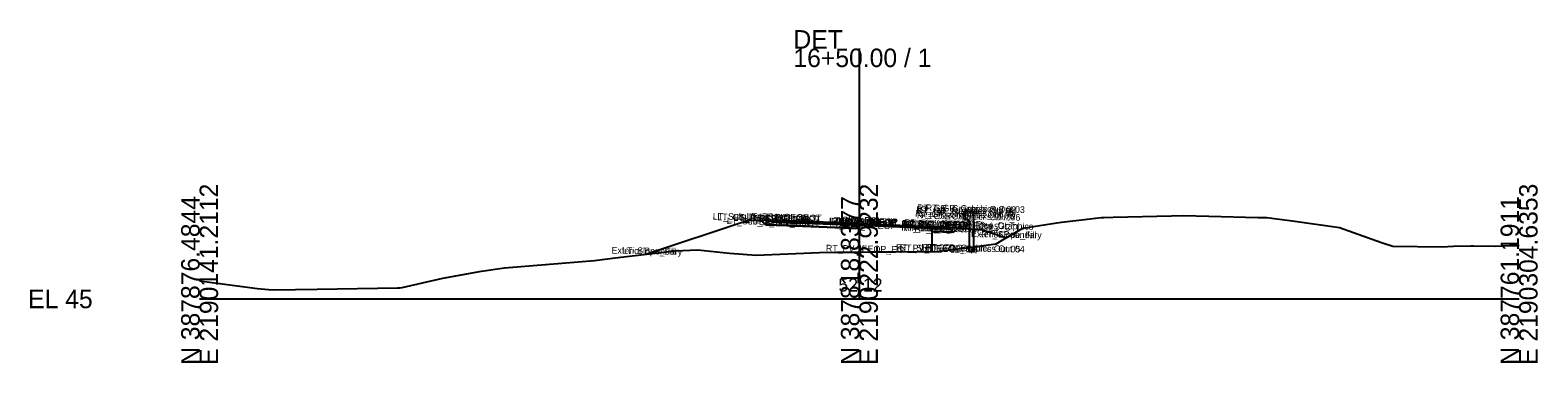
# Model space of a CAD drawing. Extents: x -26 to 1203, y -10 to 9543.
# Drawn here: x -25.7 to 202.8, y 6490.3 to 6540.8 of the extents above; entities that cross this region are included whole.
import ezdxf

# ---------------------------------------------------------------- set-up
doc = ezdxf.new("R2010")
doc.units = 0
for name, color, linetype in [('Default', 7, 'Continuous'), ('Exist CMT Pavement', 7, 'Continuous'), ('Exist Cross Section Cell', 7, 'Continuous'), ('Exist XS Center Line Elevation Label', 7, 'Continuous'), ('Exist XS Ground Line', 7, 'Continuous'), ('Prop CMT Guardrail Graphics', 7, 'Continuous'), ('Prop CMT Pvmt Course 1', 7, 'Continuous'), ('Prop CMT Pvmt Course 1 Wedge', 7, 'Continuous'), ('Prop CMT Pvmt Course 2', 7, 'Continuous'), ('Prop CMT Pvmt Course 2 Wedge', 7, 'Continuous'), ('Prop CMT Pvmt Course 3', 7, 'Continuous'), ('Prop CMT Pvmt Course 3 Wedge', 7, 'Continuous'), ('Prop CMT Pvmt Surface', 7, 'Continuous'), ('Prop CMT Pvmt Surface Shoulder', 7, 'Continuous'), ('Prop CMT Pvmt Wedge Surface 1', 7, 'Continuous'), ('Prop CMT Pvmt Wedge Surface 2', 7, 'Continuous'), ('Prop CMT Pvmt Wedge Surface 3', 7, 'Continuous'), ('Prop CMT Shld Paved Course 1', 7, 'Continuous'), ('Prop CMT Shld Paved Course 2', 7, 'Continuous'), ('Prop CMT Shld Paved Course 3', 7, 'Continuous'), ('Prop CMT Slope Grass', 7, 'Continuous'), ('Prop CMT Subgrade Earthwork', 7, 'Continuous'), ('Scratch_Level_0', 7, 'Continuous')]:
    doc.layers.add(name, color=color, linetype=linetype)

msp = doc.modelspace()

# ---------------------------------------------------------------- linework, layer by layer
at = {"layer": 'Exist CMT Pavement'}
msp.add_lwpolyline([(100, 6507.12), (111, 6507.18)], dxfattribs=at)
at = {"layer": 'Exist Cross Section Cell'}
for p, q in [((100, 6500), (100, 6537.97)), ((0, 6500), (100, 6500)), ((100, 6500), (200, 6500))]:
    msp.add_line(p, q, dxfattribs=at)
at = {"layer": 'Exist XS Ground Line'}
for p, q in [((124.76, 6510.72), (129.95, 6511.53)), ((129.95, 6511.53), (130.66, 6511.64)), ((130.66, 6511.64), (134.99, 6512.16)), ((134.99, 6512.16), (135.77, 6512.25)), ((135.77, 6512.25), (136.67, 6512.37)), ((136.67, 6512.37), (137.04, 6512.38)), ((137.04, 6512.38), (138.45, 6512.41)), ((138.45, 6512.41), (147.29, 6512.62)), ((147.29, 6512.62), (149.1, 6512.66)), ((149.1, 6512.66), (152.99, 6512.55)), ((152.99, 6512.55), (160.42, 6512.35)), ((160.42, 6512.35), (161.33, 6512.34)), ((161.33, 6512.34), (161.74, 6512.34)), ((161.74, 6512.34), (163.27, 6512.15)), ((163.27, 6512.15), (165.64, 6511.83)), ((165.64, 6511.83), (172.75, 6510.85)), ((120.74, 6508.37), (121.9, 6509.08)), ((121.9, 6509.08), (124.76, 6510.72)), ((172.75, 6510.85), (179.16, 6508.57)), ((62.97, 6506.24), (72.1, 6507.28)), ((72.1, 6507.28), (75.5, 6507.44)), ((75.5, 6507.44), (80.32, 6506.95)), ((80.32, 6506.95), (84.34, 6506.63)), ((84.34, 6506.63), (93.97, 6507.05)), ((93.97, 6507.05), (96.58, 6507.11)), ((96.58, 6507.11), (97.03, 6507.11)), ((97.03, 6507.11), (100, 6507.12)), ((100, 6507.12), (101.37, 6507.13)), ((101.37, 6507.13), (111.84, 6507.19)), ((111.84, 6507.19), (116.91, 6507.85)), ((116.91, 6507.85), (120.74, 6508.37)), ((179.16, 6508.57), (180.84, 6508.02)), ((180.84, 6508.02), (188.27, 6507.91)), ((188.27, 6507.91), (190.03, 6507.99)), ((190.03, 6507.99), (192.69, 6508.04)), ((192.69, 6508.04), (193.11, 6508.04)), ((193.11, 6508.04), (196.44, 6508.02)), ((196.44, 6508.02), (198.55, 6508.11)), ((198.55, 6508.11), (200, 6508.12)), ((36.88, 6503.17), (42.73, 6504.19)), ((42.73, 6504.19), (46.19, 6504.74)), ((46.19, 6504.74), (52.42, 6505.21)), ((52.42, 6505.21), (59.86, 6505.81)), ((59.86, 6505.81), (62.97, 6506.24)), ((0, 6502.73), (8.76, 6501.61)), ((30.36, 6501.68), (30.71, 6501.75)), ((30.71, 6501.75), (36.88, 6503.17)), ((8.76, 6501.61), (10.46, 6501.44)), ((10.46, 6501.44), (11.24, 6501.39)), ((11.24, 6501.39), (17.82, 6501.47)), ((17.82, 6501.47), (29.97, 6501.68)), ((29.97, 6501.68), (30.36, 6501.68))]:
    msp.add_line(p, q, dxfattribs=at)
at = {"layer": 'Prop CMT Guardrail Graphics'}
for points in [[(117.33, 6513.2), (116, 6513.2), (115.72, 6512.91)], [(117.33, 6507.2), (117.33, 6513.2)], [(115.72, 6512.91), (116, 6512.62)], [(116, 6512.62), (115.72, 6512.32)], [(115.72, 6512.32), (116, 6512.03), (116.66, 6512.03)], [(116.66, 6512.03), (116.66, 6507.2)], [(116.66, 6507.2), (117.33, 6507.2)]]:
    msp.add_lwpolyline(points, dxfattribs=at)
at = {"layer": 'Prop CMT Pvmt Course 1'}
for points in [[(100, 6511.43), (89, 6511.87)], [(89, 6511.87), (89, 6511.62)], [(89, 6511.62), (100, 6511.18)], [(100, 6511.18), (100, 6511.43)], [(100, 6511.43), (111, 6511)], [(100, 6511.18), (100, 6511.43)], [(111, 6510.87), (100, 6511.31)], [(100, 6511.31), (100, 6511.18), (100, 6511.18)], [(111, 6511), (111, 6510.75), (111, 6510.75), (111, 6510.87)]]:
    msp.add_lwpolyline(points, dxfattribs=at)
msp.add_lwpolyline([(100, 6511.18), (100, 6511.31), (100, 6511.31), (100, 6511.18)], close=True, dxfattribs=at)
at = {"layer": 'Prop CMT Pvmt Course 1 Wedge'}
msp.add_lwpolyline([(100, 6511.31), (111, 6510.87)], dxfattribs=at)
at = {"layer": 'Prop CMT Pvmt Course 2'}
for points in [[(89, 6511.62), (100, 6511.18)], [(100, 6511.18), (89, 6511.62)], [(89, 6511.62), (89, 6511.62)], [(100, 6511.18), (100, 6511.18)], [(111, 6510.75), (111, 6510.75)]]:
    msp.add_lwpolyline(points, dxfattribs=at)
msp.add_lwpolyline([(111, 6510.75), (111, 6510.75), (111, 6510.75)], close=True, dxfattribs=at)
at = {"layer": 'Prop CMT Pvmt Course 2 Wedge'}
msp.add_lwpolyline([(100, 6511.18), (111, 6510.75)], dxfattribs=at)
at = {"layer": 'Prop CMT Pvmt Course 3'}
for points in [[(100, 6511.18), (89, 6511.62)], [(89, 6511.62), (89, 6511.12)], [(89, 6511.12), (100, 6510.68)], [(100, 6510.68), (100, 6511.18)], [(111, 6510.75), (111, 6510.75), (111, 6510.25), (111, 6510.25)], [(111, 6510.25), (111, 6510.75)]]:
    msp.add_lwpolyline(points, dxfattribs=at)
at = {"layer": 'Prop CMT Pvmt Course 3 Wedge'}
msp.add_lwpolyline([(100, 6511.18), (111, 6510.75)], dxfattribs=at)
at = {"layer": 'Prop CMT Pvmt Surface'}
for points in [[(100, 6511.43), (89, 6511.87)], [(100, 6511.43), (111, 6511)]]:
    msp.add_lwpolyline(points, dxfattribs=at)
at = {"layer": 'Prop CMT Pvmt Surface Shoulder'}
for points in [[(89, 6511.87), (87, 6511.95)], [(111, 6511), (113, 6510.92)]]:
    msp.add_lwpolyline(points, dxfattribs=at)
at = {"layer": 'Prop CMT Pvmt Wedge Surface 1'}
for points in [[(100, 6511.31), (111, 6510.87)], [(111, 6510.75), (111, 6511)], [(111, 6510.87), (111, 6510.75), (111, 6510.75)]]:
    msp.add_lwpolyline(points, dxfattribs=at)
at = {"layer": 'Prop CMT Pvmt Wedge Surface 2'}
for points in [[(100, 6511.18), (111, 6510.75)], [(111, 6510.75), (111, 6511)]]:
    msp.add_lwpolyline(points, dxfattribs=at)
at = {"layer": 'Prop CMT Pvmt Wedge Surface 3'}
for points in [[(100, 6511.18), (111, 6510.75)], [(111, 6510.75), (111, 6511)]]:
    msp.add_lwpolyline(points, dxfattribs=at)
at = {"layer": 'Prop CMT Shld Paved Course 1'}
for points in [[(89, 6511.87), (87, 6511.95), (86.76, 6511.71)], [(86.76, 6511.71), (89, 6511.62)], [(89, 6511.62), (89, 6511.87)], [(111, 6511), (113, 6510.92), (113.26, 6510.66)], [(111, 6510.75), (111, 6511)], [(113.26, 6510.66), (111, 6510.75)]]:
    msp.add_lwpolyline(points, dxfattribs=at)
at = {"layer": 'Prop CMT Shld Paved Course 2'}
for points in [[(89, 6511.62), (86.76, 6511.71)], [(86.76, 6511.71), (86.76, 6511.71)], [(86.76, 6511.71), (89, 6511.62)], [(89, 6511.62), (89, 6511.62)], [(111, 6510.75), (113.26, 6510.66)], [(113.26, 6510.66), (111, 6510.75)], [(111, 6510.75), (111, 6510.75)], [(113.26, 6510.66), (113.26, 6510.66)]]:
    msp.add_lwpolyline(points, dxfattribs=at)
at = {"layer": 'Prop CMT Shld Paved Course 3'}
for points in [[(89, 6511.62), (86.76, 6511.71), (86.26, 6511.73), (85.78, 6511.24)], [(85.78, 6511.24), (89, 6511.12)], [(89, 6511.12), (89, 6511.62)], [(111, 6510.75), (113.26, 6510.66), (113.76, 6510.64), (114.28, 6510.12)], [(111, 6510.25), (111, 6510.75)], [(114.28, 6510.12), (111, 6510.25)]]:
    msp.add_lwpolyline(points, dxfattribs=at)
at = {"layer": 'Prop CMT Slope Grass'}
for points in [[(87, 6511.95), (83, 6511.86), (67.77, 6506.79)], [(113, 6510.92), (115.72, 6510.7)], [(115.72, 6510.7), (118.72, 6510.46)], [(118.72, 6510.46), (122.26, 6509.28)]]:
    msp.add_lwpolyline(points, dxfattribs=at)
at = {"layer": 'Prop CMT Subgrade Earthwork'}
for points in [[(85.78, 6511.24), (85.12, 6511.91)], [(89, 6511.12), (85.78, 6511.24)], [(100, 6510.68), (89, 6511.12)], [(111, 6510.25), (111, 6510.25)], [(111, 6510.25), (111, 6507.18)], [(111, 6510.25), (114.28, 6510.12)], [(114.28, 6510.12), (114.93, 6510.76)]]:
    msp.add_lwpolyline(points, dxfattribs=at)

# ---------------------------------------------------------------- texts
at = {"layer": 'Default'}
msp.add_text('-', height=0.0001, dxfattribs=at).set_placement((0, 6500))
at = {"layer": 'Exist Cross Section Cell'}
for s, p in [('DET', (90, 6537.97)), ('16+50.00 / 1', (90, 6535.17)), ('EL 45', (-26, 6498.6))]:
    msp.add_text(s, height=2.8, dxfattribs=at).set_placement(p)
for s, p in [('N 387876.4844', (0, 6490)), ('E 2190141.2112', (2.8, 6490)), ('E 2190222.9232', (102.8, 6490)), ('E 2190304.6353', (202.8, 6490)), ('N 387818.8377', (100, 6490)), ('N 387761.1911', (200, 6490))]:
    msp.add_text(s, height=2.8, rotation=90, dxfattribs=at).set_placement(p)
at = {"layer": 'Exist XS Center Line Elevation Label'}
msp.add_text('52.12', height=2, dxfattribs=at).set_placement((96.82, 6501.12))
at = {"layer": 'Scratch_Level_0'}
for s, p in [('RT_GR_Graphics Out 08', (108.44, 6512.47)), ('RT_GR_Graphics Out 01', (108.61, 6513.05)), ('RT_GR_Graphics Out 09', (108.71, 6512.76)), ('RT_GR_Graphics Out 02', (108.74, 6513.34)), ('RT_GR_Graphics Out 03', (110.06, 6513.34)), ('LT_Sub_Trench_Out_DLT', (77.77, 6512.05)), ('LT_GS_OS_CTL', (78.46, 6511.95)), ('LT_Sub_Trench_Out', (79.89, 6511.36)), ('LT_PS3_Shelf_Out', (80.92, 6511.83)), ('LT_PS3_OEOP', (82.55, 6511.79)), ('LT_PS2_OEOP', (82.55, 6511.79)), ('LT_PS1_OEOP', (82.91, 6512.03)), ('LT_PV2_OEOT', (84.75, 6511.7)), ('LT_PV3_OEOT', (84.75, 6511.7)), ('LT_Sub_OEOT', (84.77, 6511.2)), ('LT_PV1_OEOT', (84.87, 6511.95)), ('LT_PV2_OEEOP', (95.39, 6511.27)), ('LT_PV3_OEEOP', (95.39, 6511.27)), ('LT_Sub_OEEOP', (95.42, 6510.77)), ('LT_PV1_OEEOP', (95.51, 6511.39)), ('RT_PV2_IEEOP', (95.71, 6511.26)), ('RT_PV3_IEEOP', (95.71, 6511.26)), ('LT_PV2_IEEOP', (95.77, 6511.26)), ('RT_PV1_IEEOP', (95.83, 6511.39)), ('LT_PV1_IEEOP', (95.89, 6511.39)), ('PV2_PGL', (97.35, 6511.23)), ('PV1_PGL', (97.47, 6511.48)), ('RT_PV2_OEEOP', (106.33, 6510.84)), ('RT_PV3_OEEOP', (106.33, 6510.84)), ('RT_Sub_OEEOP', (106.36, 6510.34)), ('RT_PV1_OEEOP', (106.45, 6510.96)), ('RT_GS_OS_GR_Face_Graphics', (106.66, 6510.88)), ('RT_PV3_OEOT', (106.69, 6510.83)), ('RT_PV2_OEOT', (106.69, 6510.83)), ('RT_Sub_OEOT', (106.71, 6510.33)), ('RT_PV1_OEOT', (106.81, 6511.08)), ('RT_Sub_Trench_Out_DLT', (107.52, 6510.91)), ('RT_Sub_Trench_Out', (108.33, 6510.23)), ('RT_PS3_Shelf_Out', (108.36, 6510.74)), ('RT_GR_Graphics Out 07', (108.7, 6512.17)), ('RT_PS1_OEOP', (108.85, 6511)), ('RT_PS3_OEOP', (108.99, 6510.74)), ('RT_PS2_OEOP', (108.99, 6510.74)), ('RT_GR_Graphics Out 06', (109.38, 6512.17)), ('RT_GS_OS_CTL', (114.13, 6510.55)), ('Exterior Boundary', (116.92, 6509.39)), ('RT_Slope_Fill', (118.44, 6509.36)), ('Exterior Boundary', (62.43, 6506.89)), ('LT_Slope_Fill', (64.01, 6506.86)), ('RT_PV_IEEOP_EG', (94.92, 6507.22)), ('RT_PV_OEEOP_EG', (105.54, 6507.29)), ('RT_Sub Tie Out', (106.1, 6507.28)), ('RT_GR_Graphics Out 05', (109.38, 6507.34)), ('RT_GR_Graphics Out 04', (110.04, 6507.34))]:
    msp.add_text(s, height=1, rotation=358.8836, dxfattribs=at).set_placement(p)

doc.saveas('drawing.dxf')
